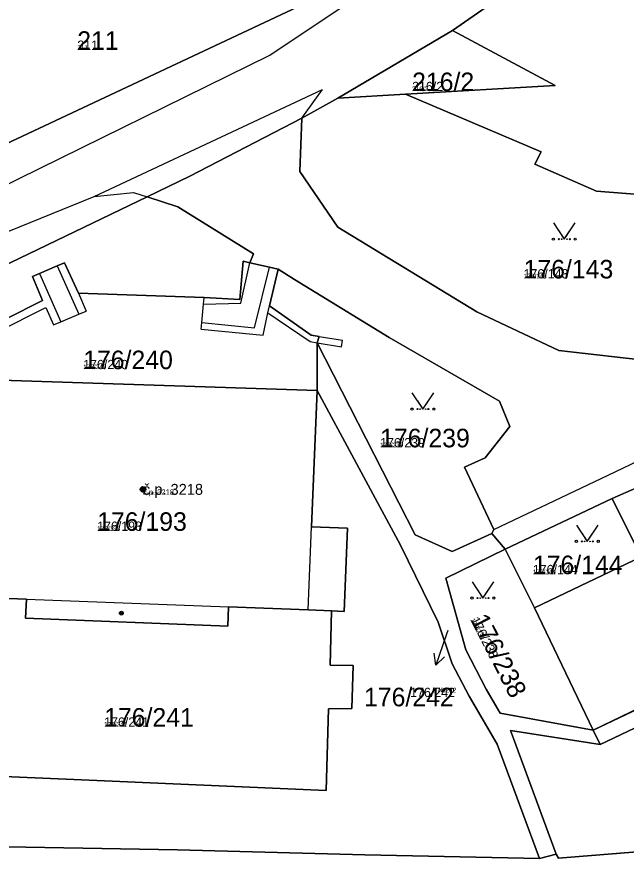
# Model space of a CAD drawing. Extents: x -759873 to -758487, y -975024 to -973516.
# Drawn here: x -759350.6 to -759294.8, y -974781.5 to -974704.3 of the extents above; entities that cross this region are included whole.
import ezdxf

# ---------------------------------------------------------------- set-up
doc = ezdxf.new("R2010")
doc.units = 0
for name, color, linetype in [('KAT_02_hranice parcel', 7, 'Continuous'), ('KAT_03_1000_st čísla parcelní', 7, 'Continuous'), ('KAT_03_1000_čísla parcelní', 7, 'Continuous'), ('KAT_03_1000_čísla popisná', 7, 'Continuous'), ('KAT_03_250_st čísla parcelní', 7, 'Continuous'), ('KAT_03_250_čísla parcelní', 7, 'Continuous'), ('KAT_03_250_čísla popisná', 7, 'Continuous'), ('KAT_03_500_st čísla parcelní', 7, 'Continuous'), ('KAT_03_500_čísla parcelní', 7, 'Continuous'), ('KAT_03_500_čísla popisná', 7, 'Continuous'), ('KAT_04_vnitřní kresba', 7, 'Continuous'), ('KAT_05_1000_značky kultur', 7, 'Continuous'), ('KAT_05_250_značky kultur', 7, 'Continuous'), ('KAT_05_500_značky kultur', 7, 'Continuous'), ('KAT_07_1000_značky budov', 7, 'Continuous'), ('KAT_07_250_značky budov', 7, 'Continuous'), ('KAT_07_500_značky budov', 7, 'Continuous'), ('KAT_12_pomocná šipka', 7, 'Continuous'), ('KAT_14_plocha_budovy', 7, 'Continuous'), ('KAT_14_plocha_pozemek', 7, 'Continuous')]:
    doc.layers.add(name, color=color, linetype=linetype)

msp = doc.modelspace()

# ---------------------------------------------------------------- linework, layer by layer
at = {"layer": 'KAT_02_hranice parcel'}
for p, q in [((-759321.22, -974711.76), (-759310.73, -974705.56)), ((-759321.22, -974711.76), (-759324.54, -974713.59)), ((-759315.02, -974711.39), (-759321.22, -974711.76)), ((-759323.14, -974738.53), (-759323.13, -974734.15)), ((-759293.88, -974747.43), (-759296.1, -974748.42)), ((-759296.1, -974748.42), (-759305.91, -974753.05)), ((-759307.12, -974751.61), (-759305.91, -974753.05)), ((-759305.91, -974753.05), (-759303.23, -974758.44)), ((-759303.23, -974758.44), (-759297.83, -974769.65)), ((-759297.83, -974769.65), (-759278.22, -974760.18)), ((-759297.83, -974769.65), (-759297.2, -974770.95)), ((-759301.24, -974780.99), (-759302.75, -974781.4))]:
    msp.add_line(p, q, dxfattribs=at)
for points in [[(-759310.73, -974705.56), (-759302.37, -974699.71), (-759294.92, -974692.6), (-759285.8, -974680.51), (-759284.4, -974678.27), (-759283.65, -974677.06)], [(-759318.71, -974700.17), (-759321.9, -974701.95), (-759356.72, -974718.32)], [(-759324.54, -974713.59), (-759324.7, -974718.47), (-759321.24, -974723.55), (-759308.51, -974731.31), (-759301, -974734.87), (-759292.4, -974735.85), (-759283.89, -974733), (-759285.66, -974728.53), (-759259.71, -974716.22), (-759235.11, -974704.47)], [(-759310.73, -974705.56), (-759301.33, -974710.58), (-759315.02, -974711.39)], [(-759297.2, -974770.95), (-759269.53, -974757.78), (-759268.81, -974757.44), (-759237.44, -974742.52), (-759232.51, -974740.14), (-759189.23, -974719.52), (-759188.5, -974719.17), (-759159.12, -974705.45)], [(-759274.71, -974708.8), (-759275.08, -974710), (-759278.97, -974715.28), (-759284.55, -974719.08), (-759290.54, -974720.81), (-759297.53, -974720.28), (-759303.18, -974717.78), (-759302.61, -974716.66), (-759315.02, -974711.39)], [(-759301.24, -974780.99), (-759301.03, -974781.35), (-759293.44, -974780.74), (-759288.26, -974778.87), (-759268.89, -974769.51), (-759250.85, -974760.82), (-759247.34, -974759.1), (-759236.73, -974753.99), (-759224.73, -974748.18), (-759206.51, -974739.34), (-759188.27, -974730.61), (-759177.27, -974725.26), (-759160.55, -974717.22), (-759156.31, -974714.42), (-759154.33, -974710.16)], [(-759324.54, -974713.59), (-759334.79, -974718.9), (-759338.69, -974720.79)], [(-759338.69, -974720.79), (-759368.71, -974735.24), (-759393.08, -974746.85), (-759424.93, -974762.5)], [(-759338.69, -974720.79), (-759335.9, -974721.69), (-759328.95, -974726.01), (-759329.3, -974726.82)], [(-759361.58, -974736.96), (-759348.29, -974730.29), (-759349.19, -974728.08), (-759348.55, -974727.8), (-759346.93, -974727.1), (-759346.28, -974726.82), (-759345, -974729.6), (-759333.48, -974730.01), (-759330.21, -974730.19), (-759329.89, -974726.69), (-759329.3, -974726.82)], [(-759329.3, -974726.82), (-759327.5, -974727.23), (-759326.71, -974727.4)], [(-759326.71, -974727.4), (-759327.48, -974730.77), (-759323.68, -974733.46), (-759322.94, -974733.58), (-759323.13, -974734.15)], [(-759326.71, -974727.4), (-759325.2, -974728.35), (-759316.52, -974733.67), (-759306.42, -974739.5), (-759305.49, -974741.83), (-759307.75, -974744.69), (-759309.63, -974745.55), (-759306.95, -974751.27), (-759307.12, -974751.61)], [(-759323.13, -974734.15), (-759314.14, -974751.75), (-759310.75, -974753.27), (-759307.12, -974751.61)], [(-759323.14, -974738.53), (-759353.97, -974737.52), (-759354.04, -974739.15), (-759357.32, -974739), (-759357.49, -974742.92)], [(-759321.81, -974758.71), (-759320.64, -974758.76), (-759320.34, -974751.15), (-759323.64, -974751.02), (-759323.14, -974738.53)], [(-759302.75, -974781.4), (-759306.63, -974770.93), (-759309.21, -974766.51), (-759310.75, -974763.57), (-759312.05, -974759.76), (-759315.5, -974752.69), (-759323.14, -974738.53)], [(-759296.1, -974748.42), (-759293.45, -974753.77), (-759303.23, -974758.44)], [(-759305.91, -974753.05), (-759311.34, -974755.71), (-759309.5, -974762.28), (-759307.66, -974765.88), (-759306.37, -974768.07), (-759297.83, -974769.65)], [(-759354.74, -974757.45), (-759349.74, -974757.64), (-759349.83, -974759.39), (-759331.3, -974760.1), (-759331.26, -974758.35), (-759323.94, -974758.63), (-759321.81, -974758.71)], [(-759321.81, -974758.71), (-759321.95, -974763.67), (-759319.84, -974763.72), (-759319.94, -974767.65), (-759322.08, -974767.68), (-759322.29, -974775.16), (-759345.4, -974774.17), (-759355.39, -974773.73)], [(-759424.93, -974762.5), (-759425.59, -974765.85), (-759424.23, -974769.73), (-759420.74, -974774.82), (-759416.74, -974776.65), (-759408.58, -974778.44), (-759401.14, -974779.15), (-759383.31, -974779.68), (-759360.24, -974780.18), (-759335.92, -974780.61), (-759318.75, -974781.06), (-759302.75, -974781.4)], [(-759297.2, -974770.95), (-759305.42, -974769.66), (-759305.13, -974770.39), (-759301.24, -974780.99)]]:
    msp.add_lwpolyline(points, dxfattribs=at)
at = {"layer": 'KAT_03_1000_čísla popisná'}
msp.add_circle((-759339.08, -974747.58), 0.25, dxfattribs=at)
at = {"layer": 'KAT_03_250_čísla popisná'}
msp.add_circle((-759339.08, -974747.58), 0.0625, dxfattribs=at)
at = {"layer": 'KAT_03_500_čísla popisná'}
msp.add_circle((-759339.08, -974747.58), 0.125, dxfattribs=at)
at = {"layer": 'KAT_04_vnitřní kresba'}
for p, q in [((-759327.47, -974707.8), (-759300.76, -974689.96)), ((-759354.42, -974721.07), (-759327.47, -974707.8)), ((-759343.54, -974720.75), (-759322.64, -974710.94)), ((-759324.54, -974713.59), (-759322.64, -974710.94)), ((-759343.54, -974720.75), (-759339.95, -974720.38)), ((-759339.95, -974720.38), (-759338.69, -974720.79)), ((-759352.37, -974724.34), (-759343.54, -974720.75)), ((-759346.93, -974727.1), (-759344.96, -974731.54)), ((-759330.13, -974730.53), (-759329.3, -974726.82)), ((-759328.86, -974732.79), (-759327.5, -974727.23)), ((-759296.46, -974746.27), (-759255.11, -974726.67)), ((-759348.55, -974727.8), (-759346.61, -974732.24)), ((-759345, -974729.6), (-759344.3, -974731.25)), ((-759333.54, -974730.61), (-759333.48, -974730.01)), ((-759361.27, -974737.59), (-759347.98, -974730.92)), ((-759347.98, -974730.92), (-759347.27, -974732.52)), ((-759344.96, -974731.54), (-759344.3, -974731.25)), ((-759333.7, -974732.31), (-759333.54, -974730.61)), ((-759333.54, -974730.61), (-759330.13, -974730.53)), ((-759327.63, -974731.4), (-759327.48, -974730.77)), ((-759346.61, -974732.24), (-759344.96, -974731.54)), ((-759328.07, -974733.47), (-759327.63, -974731.4)), ((-759327.63, -974731.4), (-759323.77, -974734.05)), ((-759347.27, -974732.52), (-759346.61, -974732.24)), ((-759333.76, -974732.91), (-759333.7, -974732.31)), ((-759333.7, -974732.31), (-759328.86, -974732.79)), ((-759333.76, -974732.91), (-759328.07, -974733.47)), ((-759323.77, -974734.05), (-759323.13, -974734.15)), ((-759323.13, -974734.15), (-759320.9, -974734.51)), ((-759322.94, -974733.58), (-759320.81, -974733.92)), ((-759320.9, -974734.51), (-759320.81, -974733.92)), ((-759306.95, -974751.27), (-759296.46, -974746.27)), ((-759323.94, -974758.63), (-759323.64, -974751.02)), ((-759349.74, -974757.64), (-759331.26, -974758.35))]:
    msp.add_line(p, q, dxfattribs=at)
at = {"layer": 'KAT_05_1000_značky kultur'}
for points in [[(-759301.49, -974723.159), (-759300.49, -974724.66), (-759299.49, -974723.159)], [(-759314.44, -974738.729), (-759313.44, -974740.23), (-759312.44, -974738.729)], [(-759299.38, -974750.849), (-759298.38, -974752.35), (-759297.38, -974750.849)], [(-759308.94, -974756.039), (-759307.94, -974757.54), (-759306.94, -974756.039)]]:
    msp.add_lwpolyline(points, dxfattribs=at)
for centre in [(-759301.49, -974724.659), (-759299.49, -974724.659), (-759314.44, -974740.229), (-759312.44, -974740.229), (-759299.38, -974752.349), (-759297.38, -974752.349), (-759308.94, -974757.539), (-759306.94, -974757.539)]:
    msp.add_circle(centre, 0.1, dxfattribs=at)
at = {"layer": 'KAT_05_250_značky kultur'}
for points in [[(-759300.74, -974724.285), (-759300.49, -974724.66), (-759300.24, -974724.285)], [(-759313.69, -974739.855), (-759313.44, -974740.23), (-759313.19, -974739.855)], [(-759298.63, -974751.975), (-759298.38, -974752.35), (-759298.13, -974751.975)], [(-759308.19, -974757.165), (-759307.94, -974757.54), (-759307.69, -974757.165)]]:
    msp.add_lwpolyline(points, dxfattribs=at)
for centre in [(-759300.74, -974724.66), (-759300.24, -974724.66), (-759313.69, -974740.23), (-759313.19, -974740.23), (-759298.63, -974752.35), (-759298.13, -974752.35), (-759308.19, -974757.54), (-759307.69, -974757.54)]:
    msp.add_circle(centre, 0.025, dxfattribs=at)
at = {"layer": 'KAT_05_500_značky kultur'}
for points in [[(-759300.99, -974723.91), (-759300.49, -974724.66), (-759299.99, -974723.91)], [(-759313.94, -974739.48), (-759313.44, -974740.23), (-759312.94, -974739.48)], [(-759298.88, -974751.6), (-759298.38, -974752.35), (-759297.88, -974751.6)], [(-759308.44, -974756.79), (-759307.94, -974757.54), (-759307.44, -974756.79)]]:
    msp.add_lwpolyline(points, dxfattribs=at)
for centre in [(-759300.99, -974724.66), (-759299.99, -974724.66), (-759313.94, -974740.23), (-759312.94, -974740.23), (-759298.88, -974752.35), (-759297.88, -974752.35), (-759308.44, -974757.54), (-759307.44, -974757.54)]:
    msp.add_circle(centre, 0.05, dxfattribs=at)
at = {"layer": 'KAT_07_1000_značky budov'}
for centre in [(-759339.087, -974747.579), (-759341.057, -974758.919)]:
    msp.add_circle(centre, 0.175, dxfattribs=at)
at = {"layer": 'KAT_07_250_značky budov'}
for centre in [(-759339.082, -974747.58), (-759341.052, -974758.92)]:
    msp.add_circle(centre, 0.0437, dxfattribs=at)
at = {"layer": 'KAT_07_500_značky budov'}
for centre in [(-759339.083, -974747.58), (-759341.053, -974758.92)]:
    msp.add_circle(centre, 0.0875, dxfattribs=at)
at = {"layer": 'KAT_12_pomocná šipka'}
for p, q in [((-759311.17, -974760.5), (-759311.29, -974760.86)), ((-759311.29, -974760.86), (-759312.267, -974763.697)), ((-759312.267, -974763.697), (-759312.414, -974762.588)), ((-759312.267, -974763.697), (-759311.468, -974762.914))]:
    msp.add_line(p, q, dxfattribs=at)
at = {"layer": 'KAT_14_plocha_budovy'}
for points in [[(-759353.97, -974737.52), (-759354.04, -974739.15), (-759354.21, -974743.08), (-759354.3, -974745.08), (-759354.73, -974754.83), (-759354.74, -974757.45), (-759349.74, -974757.64), (-759331.26, -974758.35), (-759323.94, -974758.63), (-759323.64, -974751.02), (-759323.14, -974738.53)], [(-759303.23, -974758.44), (-759297.83, -974769.65), (-759278.22, -974760.18), (-759258.52, -974750.77), (-759263.84, -974739.63), (-759272.15, -974743.6), (-759273.96, -974744.46), (-759283.54, -974749.04), (-759291.32, -974752.75), (-759293.45, -974753.77)]]:
    msp.add_lwpolyline(points, close=True, dxfattribs=at)
at = {"layer": 'KAT_14_plocha_pozemek'}
for points in [[(-759272.2, -974639.41), (-759281.65, -974658.4), (-759285.91, -974664.61), (-759289.93, -974671.68), (-759292.94, -974676.6), (-759294.74, -974679.54), (-759302.19, -974688.3), (-759308.07, -974693.53), (-759315.75, -974698.43), (-759315.34, -974698.65), (-759317.07, -974700.43), (-759318.71, -974700.17), (-759321.9, -974701.95), (-759356.72, -974718.32), (-759357.54, -974720.88), (-759360.14, -974721.06), (-759370.17, -974725.64), (-759407.29, -974742.88), (-759417.45, -974747.54), (-759420.68, -974749.02), (-759440.41, -974758.08), (-759470.53, -974765.37)], [(-759459.82, -974776.57), (-759452, -974776.85), (-759432.32, -974766.17), (-759431.64, -974765.8), (-759424.93, -974762.5), (-759393.08, -974746.85), (-759368.71, -974735.24), (-759338.69, -974720.79), (-759334.79, -974718.9), (-759324.54, -974713.59), (-759321.22, -974711.76), (-759310.73, -974705.56), (-759302.37, -974699.71), (-759294.92, -974692.6), (-759285.8, -974680.51), (-759284.4, -974678.27), (-759283.65, -974677.06), (-759283.26, -974675.23), (-759282.29, -974673.85), (-759279.86, -974670.39), (-759274.06, -974660.4), (-759274.03, -974662.11), (-759273.99, -974664.17)], [(-759159.12, -974705.45), (-759188.5, -974719.17), (-759189.23, -974719.52), (-759232.51, -974740.14), (-759237.44, -974742.52), (-759268.81, -974757.44), (-759269.53, -974757.78), (-759297.2, -974770.95), (-759305.42, -974769.66), (-759305.13, -974770.39), (-759301.24, -974780.99), (-759301.03, -974781.35), (-759293.44, -974780.74), (-759288.26, -974778.87), (-759268.89, -974769.51), (-759250.85, -974760.82), (-759247.34, -974759.1), (-759236.73, -974753.99), (-759224.73, -974748.18), (-759206.51, -974739.34), (-759188.27, -974730.61), (-759177.27, -974725.26), (-759160.55, -974717.22)], [(-759290.54, -974720.81), (-759297.53, -974720.28), (-759303.18, -974717.78), (-759302.61, -974716.66), (-759315.02, -974711.39), (-759321.22, -974711.76), (-759324.54, -974713.59), (-759324.7, -974718.47), (-759321.24, -974723.55), (-759308.51, -974731.31), (-759301, -974734.87), (-759292.4, -974735.85)], [(-759292.4, -974735.85), (-759301, -974734.87), (-759308.51, -974731.31), (-759321.24, -974723.55), (-759324.7, -974718.47), (-759324.54, -974713.59), (-759334.79, -974718.9), (-759338.69, -974720.79), (-759335.9, -974721.69), (-759328.95, -974726.01), (-759329.3, -974726.82), (-759327.5, -974727.23), (-759326.71, -974727.4), (-759325.2, -974728.35), (-759316.52, -974733.67), (-759306.42, -974739.5), (-759305.49, -974741.83), (-759307.75, -974744.69), (-759309.63, -974745.55), (-759306.95, -974751.27), (-759307.12, -974751.61), (-759305.91, -974753.05), (-759296.1, -974748.42), (-759293.88, -974747.43)], [(-759361.58, -974736.96), (-759348.29, -974730.29), (-759349.19, -974728.08), (-759348.55, -974727.8), (-759346.93, -974727.1), (-759346.28, -974726.82), (-759345, -974729.6), (-759333.48, -974730.01), (-759330.21, -974730.19), (-759329.89, -974726.69), (-759329.3, -974726.82), (-759328.95, -974726.01), (-759335.9, -974721.69), (-759338.69, -974720.79), (-759368.71, -974735.24)], [(-759353.97, -974737.52), (-759323.14, -974738.53), (-759323.13, -974734.15), (-759322.94, -974733.58), (-759323.68, -974733.46), (-759327.48, -974730.77), (-759326.71, -974727.4), (-759327.5, -974727.23), (-759329.3, -974726.82), (-759329.89, -974726.69), (-759330.21, -974730.19), (-759333.48, -974730.01), (-759345, -974729.6), (-759346.28, -974726.82), (-759346.93, -974727.1), (-759348.55, -974727.8), (-759349.19, -974728.08), (-759348.29, -974730.29), (-759361.58, -974736.96)], [(-759360.24, -974780.18), (-759335.92, -974780.61), (-759318.75, -974781.06), (-759302.75, -974781.4), (-759306.63, -974770.93), (-759309.21, -974766.51), (-759310.75, -974763.57), (-759312.05, -974759.76), (-759315.5, -974752.69), (-759323.14, -974738.53), (-759323.64, -974751.02), (-759320.34, -974751.15), (-759320.64, -974758.76), (-759321.81, -974758.71), (-759321.95, -974763.67), (-759319.84, -974763.72), (-759319.94, -974767.65), (-759322.08, -974767.68), (-759322.29, -974775.16), (-759345.4, -974774.17), (-759355.39, -974773.73)], [(-759293.44, -974780.74), (-759301.03, -974781.35), (-759301.24, -974780.99), (-759302.75, -974781.4), (-759318.75, -974781.06), (-759335.92, -974780.61), (-759360.24, -974780.18), (-759383.31, -974779.68), (-759401.14, -974779.15), (-759408.58, -974778.44), (-759416.74, -974776.65), (-759420.74, -974774.82), (-759424.23, -974769.73), (-759425.59, -974765.85), (-759424.93, -974762.5), (-759431.64, -974765.8), (-759432.32, -974766.17), (-759431.12, -974766.84), (-759428.57, -974769.5), (-759418.5, -974784.52)]]:
    msp.add_lwpolyline(points, dxfattribs=at)
for points in [[(-759301.33, -974710.58), (-759315.02, -974711.39), (-759302.61, -974716.66), (-759303.18, -974717.78), (-759297.53, -974720.28), (-759290.54, -974720.81), (-759284.55, -974719.08), (-759278.97, -974715.28), (-759275.08, -974710), (-759274.71, -974708.8), (-759273.27, -974704.19), (-759273.51, -974697.17), (-759275.8, -974691.27), (-759277.1, -974691.83), (-759277.83, -974690.95), (-759282.64, -974685.99), (-759283.98, -974682.52), (-759284.09, -974679.16), (-759283.65, -974677.06), (-759284.4, -974678.27), (-759285.8, -974680.51), (-759294.92, -974692.6), (-759302.37, -974699.71), (-759310.73, -974705.56)], [(-759354.37, -974710.98), (-759356.72, -974718.32), (-759321.9, -974701.95), (-759318.71, -974700.17), (-759354.98, -974694.48), (-759354.76, -974700.34)], [(-759189.23, -974719.52), (-759188.5, -974719.17), (-759159.12, -974705.45), (-759160.58, -974704.45), (-759179.67, -974713.25), (-759199.38, -974722.66), (-759219.12, -974732.06), (-759238.84, -974741.43), (-759258.52, -974750.77), (-759278.22, -974760.18), (-759297.83, -974769.65), (-759297.2, -974770.95), (-759269.53, -974757.78), (-759268.81, -974757.44), (-759237.44, -974742.52), (-759232.51, -974740.14)], [(-759321.22, -974711.76), (-759315.02, -974711.39), (-759301.33, -974710.58), (-759310.73, -974705.56)], [(-759322.94, -974733.58), (-759323.13, -974734.15), (-759314.14, -974751.75), (-759310.75, -974753.27), (-759307.12, -974751.61), (-759306.95, -974751.27), (-759309.63, -974745.55), (-759307.75, -974744.69), (-759305.49, -974741.83), (-759306.42, -974739.5), (-759316.52, -974733.67), (-759325.2, -974728.35), (-759326.71, -974727.4), (-759327.48, -974730.77), (-759323.68, -974733.46)], [(-759297.2, -974770.95), (-759297.83, -974769.65), (-759306.37, -974768.07), (-759307.66, -974765.88), (-759309.5, -974762.28), (-759311.34, -974755.71), (-759305.91, -974753.05), (-759307.12, -974751.61), (-759310.75, -974753.27), (-759314.14, -974751.75), (-759323.13, -974734.15), (-759323.14, -974738.53), (-759315.5, -974752.69), (-759312.05, -974759.76), (-759310.75, -974763.57), (-759309.21, -974766.51), (-759306.63, -974770.93), (-759302.75, -974781.4), (-759301.24, -974780.99), (-759305.13, -974770.39), (-759305.42, -974769.66)], [(-759320.34, -974751.15), (-759323.64, -974751.02), (-759323.14, -974738.53), (-759353.97, -974737.52), (-759354.04, -974739.15), (-759357.32, -974739), (-759357.49, -974742.92), (-759354.21, -974743.08), (-759354.3, -974745.08), (-759354.73, -974754.83), (-759354.74, -974757.45), (-759349.74, -974757.64), (-759349.83, -974759.39), (-759331.3, -974760.1), (-759331.26, -974758.35), (-759323.94, -974758.63), (-759321.81, -974758.71), (-759320.64, -974758.76)], [(-759293.88, -974747.43), (-759296.1, -974748.42), (-759293.45, -974753.77), (-759303.23, -974758.44), (-759297.83, -974769.65), (-759278.22, -974760.18), (-759283.54, -974749.04), (-759291.32, -974752.75)], [(-759296.1, -974748.42), (-759305.91, -974753.05), (-759303.23, -974758.44), (-759293.45, -974753.77)], [(-759309.5, -974762.28), (-759307.66, -974765.88), (-759306.37, -974768.07), (-759297.83, -974769.65), (-759303.23, -974758.44), (-759305.91, -974753.05), (-759311.34, -974755.71)], [(-759355.03, -974764.72), (-759355.39, -974773.73), (-759345.4, -974774.17), (-759322.29, -974775.16), (-759322.08, -974767.68), (-759319.94, -974767.65), (-759319.84, -974763.72), (-759321.95, -974763.67), (-759321.81, -974758.71), (-759323.94, -974758.63), (-759331.26, -974758.35), (-759331.3, -974760.1), (-759349.83, -974759.39), (-759349.74, -974757.64), (-759354.74, -974757.45)]]:
    msp.add_lwpolyline(points, close=True, dxfattribs=at)

# ---------------------------------------------------------------- texts
at = {"layer": 'KAT_03_1000_st čísla parcelní'}
msp.add_text('176/193', height=1.7, dxfattribs=at).set_placement((-759343.28, -974751.38))
at = {"layer": 'KAT_03_1000_čísla parcelní'}
for s, p in [('211', (-759345.1, -974707.32)), ('216/2', (-759314.43, -974711.1)), ('176/143', (-759304.22, -974728.26)), ('176/240', (-759344.56, -974736.57)), ('176/239', (-759317.36, -974743.73)), ('176/144', (-759303.37, -974755.35)), ('176/242', (-759318.836, -974767.453)), ('176/241', (-759342.64, -974769.32))]:
    msp.add_text(s, height=1.7, dxfattribs=at).set_placement(p)
msp.add_text('176/238', height=1.7, rotation=297, dxfattribs=at).set_placement((-759309.107, -974759.525))
at = {"layer": 'KAT_03_1000_čísla popisná'}
msp.add_text('č.p. 3218', height=1, dxfattribs=at).set_placement((-759339.08, -974748.08))
at = {"layer": 'KAT_03_250_st čísla parcelní'}
msp.add_text('176/193', height=0.425, dxfattribs=at).set_placement((-759343.28, -974751.38))
at = {"layer": 'KAT_03_250_čísla parcelní'}
for s, p in [('211', (-759345.1, -974707.32)), ('216/2', (-759314.43, -974711.1)), ('176/143', (-759304.22, -974728.26)), ('176/240', (-759344.56, -974736.57)), ('176/239', (-759317.36, -974743.73)), ('176/144', (-759303.37, -974755.35)), ('176/242', (-759312.494, -974766.178)), ('176/241', (-759342.64, -974769.32))]:
    msp.add_text(s, height=0.425, dxfattribs=at).set_placement(p)
msp.add_text('176/238', height=0.425, rotation=297, dxfattribs=at).set_placement((-759309.107, -974759.525))
at = {"layer": 'KAT_03_250_čísla popisná'}
msp.add_text('č.p. 3218', height=0.25, dxfattribs=at).set_placement((-759339.08, -974748.08))
at = {"layer": 'KAT_03_500_st čísla parcelní'}
msp.add_text('176/193', height=0.85, dxfattribs=at).set_placement((-759343.28, -974751.38))
at = {"layer": 'KAT_03_500_čísla parcelní'}
for s, p in [('211', (-759345.1, -974707.32)), ('216/2', (-759314.43, -974711.1)), ('176/143', (-759304.22, -974728.26)), ('176/240', (-759344.56, -974736.57)), ('176/239', (-759317.36, -974743.73)), ('176/144', (-759303.37, -974755.35)), ('176/242', (-759314.608, -974766.603)), ('176/241', (-759342.64, -974769.32))]:
    msp.add_text(s, height=0.85, dxfattribs=at).set_placement(p)
msp.add_text('176/238', height=0.85, rotation=297, dxfattribs=at).set_placement((-759309.107, -974759.525))
at = {"layer": 'KAT_03_500_čísla popisná'}
msp.add_text('č.p. 3218', height=0.5, dxfattribs=at).set_placement((-759339.08, -974748.08))

doc.saveas('drawing.dxf')
